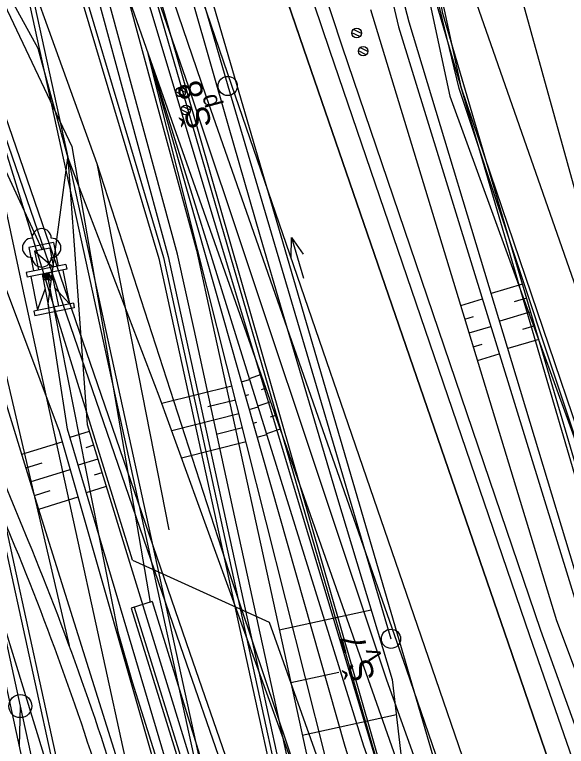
# Model space of a CAD drawing. Extents: x -439827 to -439102, y -1131353 to -1129707.
# Drawn here: x -439580.11 to -439551.42, y -1129995.75 to -1129957.67 of the extents above; entities that cross this region are included whole.
import ezdxf

# ---------------------------------------------------------------- set-up
doc = ezdxf.new("R2010")
doc.units = 0
for name, color, linetype in [('Vrstva 1', 7, 'Continuous'), ('Vrstva 10', 7, 'Continuous'), ('Vrstva 11', 7, 'Continuous'), ('Vrstva 15', 7, 'Continuous'), ('Vrstva 18', 7, 'Continuous'), ('Vrstva 20', 7, 'Continuous'), ('Vrstva 24', 7, 'Continuous'), ('Vrstva 25', 7, 'Continuous'), ('Vrstva 36', 7, 'Continuous'), ('Vrstva 4', 7, 'Continuous'), ('Vrstva 42', 7, 'Continuous'), ('Vrstva 45', 7, 'Continuous'), ('Vrstva 47', 7, 'Continuous'), ('Vrstva 49', 7, 'Continuous'), ('Vrstva 5', 7, 'Continuous'), ('Vrstva 50', 7, 'Continuous'), ('Vrstva 52', 7, 'Continuous'), ('Vrstva 57', 7, 'Continuous'), ('Vrstva 59', 7, 'Continuous'), ('Vrstva 61', 7, 'Continuous'), ('Vrstva 62', 7, 'Continuous'), ('Vrstva 63', 7, 'Continuous'), ('Vrstva 9', 7, 'Continuous')]:
    doc.layers.add(name, color=color, linetype=linetype)

# ---------------------------------------------------------------- blocks, each defined once
blk = doc.blocks.new('LAPAC_')
at = {"layer": 'Vrstva 1'}
for p, q in [((5, 10.49), (5, -10.5)), ((5, 10.49), (7.51, 10.49)), ((7.51, 10.49), (7.53, -10.5)), ((7.51, 8.5), (25.51, 8.49)), ((25.49, 8.48), (15.5, 2.5)), ((25.5, 10.47), (28, 10.48)), ((25.5, 10.47), (25.5, -10.5)), ((28, 10.48), (28.01, -10.48)), ((-7.5, 6.5), (4.99, 6.51)), ((-7.5, 6.5), (-7.49, -6.51)), ((-4.98, 4), (-5, -4)), ((-5, -4), (5, 4)), ((-4.98, 4), (5.01, 4)), ((7.51, 2.5), (25.5, 2.51)), ((7.51, 0), (28, 0)), ((7.51, -2.49), (25.5, -2.51)), ((25.51, -8.49), (15.52, -2.5)), ((-7.49, -6.51), (4.99, -6.51)), ((-5, -4), (4.99, -4)), ((5, -10.5), (7.53, -10.5)), ((7.51, -8.5), (25.51, -8.49)), ((25.5, -10.5), (28.01, -10.48))]:
    blk.add_line(p, q, dxfattribs=at)
for centre in [(8.3, 1.56), (8.3, 0.16), (8.67, -0.69), (9.89, 0.34), (10.54, 1.36), (8.76, -1.44), (9.88, -1.16)]:
    blk.add_circle(centre, 1, dxfattribs=at)

msp = doc.modelspace()

# ---------------------------------------------------------------- linework, layer by layer
at = {"layer": 'Vrstva 10'}
for p, q in [((-439553.692, -1129971.7), (-439555.32, -1129972.178)), ((-439556.908, -1129972.8), (-439555.784, -1129972.456)), ((-439553.482, -1129972.42), (-439554.13, -1129972.61)), ((-439556.69, -1129973.516), (-439556.24, -1129973.38)), ((-439553.27, -1129973.138), (-439554.884, -1129973.614)), ((-439556.472, -1129974.234), (-439555.342, -1129973.892)), ((-439553.06, -1129973.858), (-439553.704, -1129974.05)), ((-439556.254, -1129974.952), (-439555.802, -1129974.814)), ((-439552.848, -1129974.578), (-439554.452, -1129975.05)), ((-439556.034, -1129975.668), (-439554.902, -1129975.324)), ((-439567.29, -1129976.404), (-439567.902, -1129976.618)), ((-439568.312, -1129976.77), (-439567.89, -1129976.65)), ((-439568.806, -1129976.996), (-439572.45, -1129977.912)), ((-439567.04, -1129977.112), (-439567.294, -1129977.2)), ((-439568.106, -1129977.492), (-439567.93, -1129977.44)), ((-439568.622, -1129977.724), (-439570.052, -1129978.084)), ((-439566.79, -1129977.82), (-439567.456, -1129978.052)), ((-439567.902, -1129978.212), (-439567.446, -1129978.084)), ((-439568.44, -1129978.45), (-439571.938, -1129979.33)), ((-439566.542, -1129978.526), (-439566.818, -1129978.624)), ((-439567.698, -1129978.934), (-439567.508, -1129978.88)), ((-439576.226, -1129979.364), (-439577.232, -1129979.674)), ((-439568.258, -1129979.178), (-439569.626, -1129979.522)), ((-439567.494, -1129979.656), (-439567, -1129979.516)), ((-439566.294, -1129979.234), (-439567.01, -1129979.486)), ((-439579.738, -1129980.544), (-439577.63, -1129979.894)), ((-439576.006, -1129980.082), (-439576.41, -1129980.206)), ((-439568.074, -1129979.906), (-439571.424, -1129980.748)), ((-439579.516, -1129981.262), (-439578.678, -1129981.002)), ((-439575.784, -1129980.798), (-439576.806, -1129981.112)), ((-439579.294, -1129981.978), (-439577.218, -1129981.338)), ((-439575.564, -1129981.514), (-439575.974, -1129981.642)), ((-439579.074, -1129982.694), (-439578.25, -1129982.438)), ((-439575.342, -1129982.23), (-439576.378, -1129982.55)), ((-439578.852, -1129983.41), (-439576.81, -1129982.77))]:
    msp.add_line(p, q, dxfattribs=at)
msp.add_lwpolyline([(-439606.718, -1129878.884), (-439599.16, -1129893.286), (-439591.48, -1129910.122), (-439589.662, -1129921.096), (-439588.348, -1129928.69), (-439584.254, -1129940.826), (-439581.56, -1129949.574), (-439575.832, -1129965.416), (-439572.088, -1129984.488)], dxfattribs=at)
at = {"layer": 'Vrstva 11'}
for points in [[(-439631.45, -1129824.71), (-439623.296, -1129852.5), (-439607.812, -1129902.52), (-439594.486, -1129945.364), (-439588.77, -1129963.69), (-439582.318, -1129984.12), (-439576.384, -1130003.39), (-439571.028, -1130020.78), (-439569.524, -1130025.24)], [(-439572.89, -1130002.436), (-439578.954, -1129983.086), (-439585.23, -1129962.72)]]:
    msp.add_lwpolyline(points, dxfattribs=at)
at = {"layer": 'Vrstva 15'}
for p, q in [((-439562.072, -1129958.642), (-439562.488, -1129958.44)), ((-439562.158, -1129958.81), (-439562.568, -1129958.608)), ((-439561.82, -1129959.754), (-439562.232, -1129959.554)), ((-439561.736, -1129959.588), (-439562.152, -1129959.384)), ((-439571.222, -1129961.716), (-439571.638, -1129961.514)), ((-439571.308, -1129961.884), (-439571.718, -1129961.682)), ((-439571.044, -1129962.814), (-439571.456, -1129962.612)), ((-439570.96, -1129962.646), (-439571.376, -1129962.444)), ((-439566.346, -1129989.687), (-439561.562, -1129988.644)), ((-439565.749, -1129992.426), (-439563.249, -1129991.881)), ((-439565.152, -1129995.165), (-439560.254, -1129994.097))]:
    msp.add_line(p, q, dxfattribs=at)
for centre in [(-439562.319, -1129958.622), (-439561.982, -1129959.566), (-439571.47, -1129961.695), (-439571.207, -1129962.626)]:
    msp.add_circle(centre, 0.25, dxfattribs=at)
at = {"layer": 'Vrstva 18'}
msp.add_line((-439579.81, -1129993.657), (-439579.872, -1129995.717), dxfattribs=at)
msp.add_lwpolyline([(-439631.86, -1129744.036), (-439633.367, -1129748.063), (-439622.927, -1129795.938), (-439612.487, -1129843.813), (-439602.046, -1129891.688), (-439593.233, -1129932.103), (-439588.758, -1129952.621), (-439584.284, -1129973.139), (-439579.81, -1129993.657), (-439575.335, -1130014.174), (-439566.386, -1130055.21)], dxfattribs=at)
msp.add_circle((-439579.81, -1129993.657), 0.6, dxfattribs=at)
at = {"layer": 'Vrstva 20'}
for points in [[(-439511.068, -1130116.958), (-439519.726, -1130091.71), (-439522.682, -1130083.14), (-439529.956, -1130061.912), (-439534.024, -1130050.036), (-439543.72, -1130021.718), (-439554.45, -1129990.362), (-439564.874, -1129960.014), (-439575.322, -1129929.52)], [(-439514.996, -1130118.198), (-439526.684, -1130084.16), (-439534.114, -1130062.498), (-439537.924, -1130051.384), (-439547.688, -1130022.904), (-439558.398, -1129991.686), (-439568.82, -1129961.348), (-439579.29, -1129930.716)]]:
    msp.add_lwpolyline(points, dxfattribs=at)
at = {"layer": 'Vrstva 24'}
msp.add_line((-439580.77, -1129965.363), (-439578.671, -1129969.901), dxfattribs=at)
at = {"layer": 'Vrstva 36'}
for p, q in [((-439573.97, -1129986.06), (-439607.88, -1129876.57)), ((-439573.27, -1129886.24), (-439556.9, -1129961.42)), ((-439556.9, -1129961.42), (-439495.89, -1130141.59)), ((-439573.97, -1129986.06), (-439572.59, -1129986.69)), ((-439572.59, -1129986.69), (-439566.87, -1129989.29)), ((-439566.87, -1129989.29), (-439527.69, -1130099.7))]:
    msp.add_line(p, q, dxfattribs=at)
at = {"layer": 'Vrstva 4'}
for points in [[(-439452.672, -1130307.618), (-439463.136, -1130278.208), (-439473.444, -1130247.422), (-439485.028, -1130212.568), (-439496.122, -1130179.246), (-439507.47, -1130146.338), (-439516.97, -1130118.814), (-439528.894, -1130083.662), (-439539.69, -1130052.08), (-439549.11, -1130024.836), (-439560.748, -1129992.304), (-439571.06, -1129961.386), (-439580.88, -1129933.18), (-439592.05, -1129899.854), (-439602.118, -1129867.674), (-439610.398, -1129839.158), (-439617.774, -1129811.206), (-439624.664, -1129780.682), (-439629.998, -1129755.268)], [(-439452.072, -1130307.172), (-439462.466, -1130278.094), (-439473.084, -1130245.544), (-439484.196, -1130212.422), (-439495.494, -1130179.146), (-439506.764, -1130146.202), (-439516.426, -1130118.702), (-439528.244, -1130083.58), (-439539.098, -1130051.84), (-439548.434, -1130024.652), (-439559.722, -1129991.734), (-439570.14, -1129961.918), (-439579.974, -1129933.094), (-439590.708, -1129900.372), (-439601.098, -1129867.326), (-439609.248, -1129839.62), (-439616.746, -1129811.082), (-439623.958, -1129780.222), (-439629.3, -1129755.206)], [(-439445.336, -1130302.16), (-439455.084, -1130275.71), (-439466.188, -1130243.062), (-439488.304, -1130177.006), (-439499.622, -1130143.812), (-439508.924, -1130116.27), (-439521.236, -1130080.8), (-439532.228, -1130049.328), (-439540.848, -1130022.744), (-439552.746, -1129989.722), (-439563.07, -1129959.314), (-439572.718, -1129930.014), (-439582.84, -1129899.55), (-439593.798, -1129865.15), (-439602.014, -1129836.3), (-439609.444, -1129808.656), (-439617.162, -1129776.376), (-439620.256, -1129761.088), (-439620.404, -1129760.148)], [(-439446.102, -1130302.732), (-439455.792, -1130275.852), (-439466.676, -1130243.236), (-439477.16, -1130212.046), (-439488.92, -1130177.274), (-439500.288, -1130144.12), (-439509.364, -1130116.456), (-439521.914, -1130080.954), (-439532.724, -1130049.53), (-439541.918, -1130022.91), (-439553.308, -1129989.992), (-439563.72, -1129959.534), (-439573.732, -1129929.866), (-439583.77, -1129899.796), (-439594.604, -1129865.112), (-439602.866, -1129836.696), (-439610.248, -1129808.686), (-439617.812, -1129776.402), (-439620.902, -1129760.638), (-439620.878, -1129760.216)]]:
    msp.add_lwpolyline(points, dxfattribs=at)
at = {"layer": 'Vrstva 42'}
for points in [[(-439571.26, -1129941.374), (-439564.874, -1129960.014), (-439554.45, -1129990.362), (-439543.72, -1130021.718), (-439534.024, -1130050.036), (-439529.956, -1130061.912), (-439522.682, -1130083.14), (-439519.726, -1130091.71), (-439511.068, -1130116.958), (-439501.606, -1130144.528), (-439490.24, -1130177.636), (-439478.968, -1130210.544), (-439457.16, -1130275.562), (-439447.35, -1130302.89), (-439445.462, -1130308.388), (-439445.064, -1130309.558), (-439434.464, -1130340.548), (-439423.826, -1130371.538), (-439413.424, -1130401.962), (-439403.314, -1130431.488), (-439395.105, -1130455.427)], [(-439399.158, -1130456.267), (-439407.226, -1130432.678), (-439417.232, -1130403.478), (-439427.682, -1130373.028), (-439438.464, -1130341.588), (-439448.942, -1130311.012), (-439450.914, -1130305.246), (-439460.972, -1130277.082), (-439482.918, -1130211.888), (-439494.254, -1130178.768), (-439505.592, -1130145.672), (-439514.996, -1130118.198), (-439526.684, -1130084.16), (-439534.114, -1130062.498), (-439537.924, -1130051.384), (-439547.688, -1130022.904), (-439558.398, -1129991.686), (-439568.82, -1129961.348), (-439575.094, -1129942.992)]]:
    msp.add_lwpolyline(points, dxfattribs=at)
at = {"layer": 'Vrstva 45'}
msp.add_lwpolyline([(-439543.649, -1130001.679), (-439556.991, -1129961.508), (-439559.4, -1129951.517), (-439562.492, -1129936.521)], dxfattribs=at)
at = {"layer": 'Vrstva 47'}
for p, q in [((-439577.344, -1129932.554), (-439569.026, -1129961.378)), ((-439569.026, -1129961.378), (-439560.537, -1129990.152))]:
    msp.add_line(p, q, dxfattribs=at)
for centre in [(-439569.026, -1129961.378), (-439560.537, -1129990.152)]:
    msp.add_circle(centre, 0.5, dxfattribs=at)
at = {"layer": 'Vrstva 49'}
msp.add_line((-439565.704, -1129969.274), (-439565.081, -1129971.38), dxfattribs=at)
msp.add_lwpolyline([(-439565.732, -1129970.325), (-439565.704, -1129969.274), (-439565.109, -1129970.141)], dxfattribs=at)
at = {"layer": 'Vrstva 5'}
for points in [[(-439524.128, -1130104.684), (-439542.36, -1130053.899), (-439560.483, -1129998.857), (-439575.708, -1129945.714), (-439590.289, -1129890.237), (-439603.222, -1129834.191), (-439614.978, -1129781.165), (-439626.657, -1129727.981), (-439631.05, -1129707.012)], [(-439600.718, -1129837.291), (-439598.553, -1129847.054), (-439596.345, -1129856.808), (-439594.102, -1129866.554), (-439591.818, -1129876.291), (-439589.494, -1129886.019), (-439587.117, -1129895.735), (-439584.686, -1129905.44), (-439582.203, -1129915.134), (-439580.689, -1129920.945), (-439579.669, -1129924.816), (-439577.082, -1129934.487), (-439574.443, -1129944.147), (-439571.752, -1129953.795), (-439569.009, -1129963.432), (-439567.338, -1129969.208), (-439566.214, -1129973.057), (-439563.366, -1129982.671), (-439560.466, -1129992.274), (-439559.308, -1130002.256), (-439558.201, -1130012.25), (-439555.572, -1130021.911), (-439553.075, -1130031.602), (-439552.175, -1130035.027)], [(-439556.38, -1130040.02), (-439557.995, -1130032.675), (-439560.126, -1130022.905), (-439562.257, -1130013.134), (-439564.387, -1130003.364), (-439566.518, -1129993.593), (-439568.649, -1129983.823), (-439570.779, -1129974.053), (-439571.634, -1129970.132), (-439573.209, -1129964.322), (-439575.828, -1129954.658), (-439578.447, -1129944.994), (-439581.067, -1129935.33), (-439583.686, -1129925.667), (-439584.73, -1129921.813), (-439586.006, -1129915.963), (-439588.136, -1129906.193), (-439590.267, -1129896.422), (-439592.398, -1129886.652), (-439594.528, -1129876.882), (-439596.659, -1129867.111), (-439598.79, -1129857.341), (-439600.92, -1129847.57), (-439603.051, -1129837.8)], [(-439587.96, -1129916.389), (-439586.682, -1129922.251), (-439585.536, -1129926.096), (-439582.673, -1129935.706), (-439579.809, -1129945.317), (-439576.946, -1129954.927), (-439574.082, -1129964.538), (-439572.364, -1129970.304), (-439571.512, -1129974.212), (-439569.381, -1129983.983), (-439567.251, -1129993.753), (-439565.12, -1130003.524), (-439562.989, -1130013.294), (-439560.859, -1130023.064), (-439558.728, -1130032.835), (-439557.22, -1130039.748), (-439556.597, -1130042.605), (-439554.467, -1130052.375), (-439552.336, -1130062.146), (-439550.379, -1130071.121)], [(-439586.934, -1129922.311), (-439586.926, -1129922.305), (-439585.78, -1129926.149), (-439582.917, -1129935.76), (-439580.053, -1129945.37), (-439577.19, -1129954.981), (-439574.327, -1129964.591), (-439572.609, -1129970.358), (-439571.756, -1129974.266), (-439569.626, -1129984.036), (-439567.495, -1129993.806), (-439565.364, -1130003.577), (-439563.234, -1130013.347), (-439561.103, -1130023.118), (-439558.972, -1130032.888), (-439557.465, -1130039.801), (-439556.842, -1130042.658), (-439554.711, -1130052.429), (-439552.58, -1130062.199), (-439551.985, -1130064.928)], [(-439584.168, -1129925.797), (-439581.549, -1129935.461), (-439578.93, -1129945.125), (-439576.311, -1129954.789), (-439573.692, -1129964.453), (-439572.12, -1129970.251), (-439571.268, -1129974.159), (-439569.137, -1129983.93), (-439567.006, -1129993.7), (-439564.876, -1130003.47), (-439562.745, -1130013.241), (-439560.614, -1130023.011), (-439558.484, -1130032.781), (-439556.976, -1130039.694), (-439556.353, -1130042.552), (-439554.222, -1130052.322), (-439552.092, -1130062.093), (-439551.741, -1130063.699)], [(-439582.703, -1129925.478), (-439580.084, -1129935.142), (-439577.464, -1129944.805), (-439574.845, -1129954.469), (-439572.226, -1129964.133), (-439570.654, -1129969.931), (-439569.802, -1129973.84), (-439567.672, -1129983.61), (-439565.541, -1129993.38), (-439563.41, -1130003.151), (-439561.28, -1130012.921), (-439559.149, -1130022.691), (-439557.018, -1130032.462), (-439555.511, -1130039.375), (-439554.888, -1130042.232), (-439552.757, -1130052.003), (-439550.626, -1130061.773), (-439548.496, -1130071.543), (-439547.692, -1130075.226)], [(-439585.829, -1129926.16), (-439583.699, -1129935.93), (-439581.568, -1129945.7), (-439579.437, -1129955.471), (-439577.307, -1129965.241), (-439576.028, -1129971.103), (-439575.176, -1129975.011), (-439573.045, -1129984.782), (-439570.915, -1129994.552), (-439568.784, -1130004.323), (-439566.653, -1130014.093), (-439564.523, -1130023.863), (-439562.392, -1130033.634), (-439560.884, -1130040.547), (-439560.261, -1130043.404), (-439558.131, -1130053.174), (-439556, -1130062.945), (-439553.869, -1130072.715), (-439551.739, -1130082.486), (-439549.608, -1130092.256), (-439547.477, -1130102.026), (-439545.347, -1130111.797)], [(-439586.073, -1129926.213), (-439583.943, -1129935.983), (-439581.812, -1129945.754), (-439579.682, -1129955.524), (-439577.551, -1129965.294), (-439576.272, -1129971.157), (-439575.42, -1129975.065), (-439573.29, -1129984.835), (-439571.159, -1129994.605), (-439569.028, -1130004.376), (-439566.898, -1130014.146), (-439564.767, -1130023.917), (-439562.636, -1130033.687), (-439561.129, -1130040.6), (-439560.506, -1130043.457), (-439558.375, -1130053.228), (-439556.244, -1130062.998), (-439554.114, -1130072.769), (-439551.983, -1130082.539), (-439549.852, -1130092.309), (-439547.722, -1130102.08), (-439545.591, -1130111.85)], [(-439589.493, -1129926.959), (-439587.362, -1129936.729), (-439585.232, -1129946.499), (-439583.101, -1129956.27), (-439580.97, -1129966.04), (-439579.692, -1129971.902), (-439578.84, -1129975.81), (-439576.709, -1129985.581), (-439574.578, -1129995.351), (-439572.448, -1130005.122), (-439570.317, -1130014.892), (-439568.186, -1130024.662), (-439566.056, -1130034.433), (-439564.548, -1130041.346), (-439563.925, -1130044.203), (-439561.794, -1130053.973), (-439559.664, -1130063.744), (-439557.533, -1130073.514), (-439555.402, -1130083.285), (-439553.272, -1130093.055), (-439551.141, -1130102.825), (-439549.01, -1130112.596)], [(-439592.913, -1129927.704), (-439590.782, -1129937.475), (-439588.651, -1129947.245), (-439586.521, -1129957.015), (-439584.39, -1129966.786), (-439583.112, -1129972.648), (-439582.259, -1129976.556), (-439580.129, -1129986.327), (-439577.998, -1129996.097), (-439575.867, -1130005.867), (-439573.737, -1130015.638), (-439571.606, -1130025.408), (-439569.475, -1130035.178), (-439567.968, -1130042.091), (-439567.345, -1130044.949), (-439565.214, -1130054.719), (-439563.083, -1130064.49), (-439560.953, -1130074.26), (-439558.822, -1130084.03), (-439556.691, -1130093.801), (-439554.561, -1130103.571), (-439552.43, -1130113.341)], [(-439594.623, -1129928.077), (-439592.492, -1129937.848), (-439590.361, -1129947.618), (-439588.231, -1129957.388), (-439586.1, -1129967.159), (-439584.822, -1129973.021), (-439583.969, -1129976.929), (-439581.839, -1129986.699), (-439579.708, -1129996.47), (-439577.577, -1130006.24), (-439575.447, -1130016.011), (-439573.316, -1130025.781), (-439571.185, -1130035.551), (-439569.678, -1130042.464), (-439569.055, -1130045.322), (-439566.924, -1130055.092), (-439564.793, -1130064.862), (-439562.663, -1130074.633), (-439560.532, -1130084.403), (-439558.401, -1130094.174), (-439556.271, -1130103.944), (-439554.14, -1130113.714)], [(-439593.157, -1129927.758), (-439591.026, -1129937.528), (-439588.896, -1129947.298), (-439586.765, -1129957.069), (-439584.634, -1129966.839), (-439583.356, -1129972.701), (-439582.504, -1129976.609), (-439580.373, -1129986.38), (-439578.242, -1129996.15), (-439576.112, -1130005.921), (-439573.981, -1130015.691), (-439571.85, -1130025.461), (-439569.72, -1130035.232), (-439568.212, -1130042.145), (-439567.589, -1130045.002), (-439565.458, -1130054.772), (-439563.328, -1130064.543), (-439561.197, -1130074.313), (-439559.066, -1130084.084), (-439556.936, -1130093.854), (-439554.805, -1130103.624), (-439552.674, -1130113.395)]]:
    msp.add_lwpolyline(points, dxfattribs=at)
at = {"layer": 'Vrstva 50'}
msp.add_line((-439578.732, -1129969.804), (-439578.66, -1129969.804), dxfattribs=at)
for centre, start, end in [((-439578.701, -1129969.303), 0, 180), ((-439579.201, -1129969.803), 90, 270), ((-439578.201, -1129969.803), 270, 90), ((-439578.701, -1129970.303), 180, 0)]:
    msp.add_arc(centre, 0.5, start, end, dxfattribs=at)
at = {"layer": 'Vrstva 52'}
for p, q in [((-439583.644, -1129950.788), (-439577.136, -1129964.538)), ((-439577.136, -1129964.538), (-439573.056, -1129988.268)), ((-439582.952, -1129966.168), (-439577.266, -1129990.506)), ((-439579.398, -1129985.038), (-439584.406, -1129972.9)), ((-439580.09, -1129985.324), (-439585.118, -1129973.142)), ((-439578.032, -1129973.138), (-439574.742, -1129989.788)), ((-439572.956, -1129988.212), (-439574.054, -1129988.552))]:
    msp.add_line(p, q, dxfattribs=at)
for points in [[(-439572.956, -1129988.212), (-439566.758, -1130008.234)], [(-439574.054, -1129988.552), (-439567.864, -1130008.55)], [(-439573.89, -1129988.502), (-439570.934, -1129998.056)], [(-439574.742, -1129989.788), (-439574, -1129992.396), (-439568.824, -1130008.828)]]:
    msp.add_lwpolyline(points, dxfattribs=at)
for radius in [151.25, 150.5]:
    msp.add_arc((-439719.223, -1130042.705), radius, 16.09885, 22.41188, dxfattribs=at)
at = {"layer": 'Vrstva 57'}
for p, q in [((-439615.997, -1129861.04), (-439571.326, -1129991.012)), ((-439571.326, -1129991.012), (-439532.649, -1130102.737))]:
    msp.add_line(p, q, dxfattribs=at)
at = {"layer": 'Vrstva 59'}
for p, q in [((-439615.666, -1129860.926), (-439570.995, -1129990.899)), ((-439570.995, -1129990.898), (-439532.318, -1130102.623))]:
    msp.add_line(p, q, dxfattribs=at)
msp.add_lwpolyline([(-439565.323, -1129925.255), (-439558.917, -1129955.176), (-439557.476, -1129961.905), (-439549.066, -1129985.001)], dxfattribs=at)
at = {"layer": 'Vrstva 61'}
for p, q in [((-439547.146, -1129994.737), (-439562.474, -1129942.35)), ((-439573.227, -1129945.323), (-439557.81, -1129998.142))]:
    msp.add_line(p, q, dxfattribs=at)
at = {"layer": 'Vrstva 62'}
msp.add_line((-439560.603, -1129998.786), (-439575.875, -1129946.07), dxfattribs=at)
at = {"layer": 'Vrstva 63'}
msp.add_lwpolyline([(-439559.899, -1130001.173), (-439569.713, -1129968.453), (-439577.958, -1129940.931), (-439581.389, -1129927.721), (-439587.866, -1129899.446), (-439590.167, -1129890.323), (-439596.266, -1129862.915), (-439602.978, -1129834.556), (-439615.089, -1129778.896), (-439619.056, -1129758.708), (-439624.106, -1129738.276), (-439628.163, -1129719.403), (-439630.545, -1129707.012)], dxfattribs=at)
at = {"layer": 'Vrstva 9'}
for p, q in [((-439573.156, -1129959.7), (-439550.138, -1130025.226)), ((-439578.362, -1129972.718), (-439577.34, -1129965.12))]:
    msp.add_line(p, q, dxfattribs=at)
for points in [[(-439615.016, -1129861.902), (-439609.016, -1129872.388), (-439598.672, -1129902.048), (-439593.08, -1129922.412), (-439591.246, -1129928.438), (-439589.858, -1129932.272), (-439590.514, -1129935.246), (-439587.63, -1129940.776), (-439586.318, -1129945.922), (-439578.898, -1129959.416), (-439577.34, -1129965.12), (-439572.6, -1129977.504), (-439565.568, -1129996.93)], [(-439539.1, -1130013.316), (-439547.926, -1129991.32), (-439557.834, -1129957.61), (-439562.26, -1129933.836), (-439563.77, -1129920.72)], [(-439563.77, -1129920.72), (-439558.54, -1129929.636), (-439556.21, -1129956.716), (-439544.386, -1129990.572), (-439539.1, -1130013.316)], [(-439583.996, -1129927.66), (-439580.782, -1129937.88), (-439573.156, -1129959.7)], [(-439558.54, -1129929.636), (-439553.914, -1129956.15), (-439544.386, -1129990.572)], [(-439565.696, -1129934.664), (-439560.14, -1129958.304), (-439549.714, -1129992.178), (-439541.66, -1130014.164), (-439534.13, -1130036.788), (-439529.434, -1130049.122)], [(-439529.434, -1130049.122), (-439533.642, -1130036.612), (-439541.214, -1130013.966), (-439549.356, -1129991.93), (-439559.582, -1129958.054), (-439565.696, -1129934.664)], [(-439588.27, -1129946.636), (-439583.488, -1129962.072), (-439583.98, -1129962.938), (-439582.788, -1129966.044), (-439577.788, -1129979.34), (-439572.16, -1129999.082), (-439566.194, -1130018.824), (-439554.92, -1130053.378)], [(-439539.78, -1130021.546), (-439551.914, -1129989.212), (-439561.59, -1129957.412)], [(-439539.976, -1130066.112), (-439543.636, -1130055.94), (-439548.718, -1130040.922), (-439555.81, -1130018.284), (-439563.966, -1129996.25), (-439573.156, -1129959.7)], [(-439573.156, -1129959.7), (-439562.928, -1129995.746), (-439555.81, -1130018.284)], [(-439573.156, -1129959.7), (-439561.968, -1129995.718), (-439554.008, -1130017.84), (-439547.068, -1130040.406), (-439541.34, -1130055.714), (-439538.356, -1130063.796)], [(-439577.34, -1129965.12), (-439576.34, -1129978.998), (-439570.26, -1129998.734), (-439564.65, -1130018.494)], [(-439575.832, -1129965.416), (-439568.974, -1129986.65), (-439562.208, -1130006.75), (-439555.4, -1130027.656), (-439549.7, -1130045.104), (-439543.224, -1130064.878), (-439534.136, -1130092.886), (-439531.324, -1130101.162), (-439529.482, -1130100.572)], [(-439554.92, -1130053.378), (-439565.49, -1130018.736), (-439571.516, -1129998.944), (-439577.362, -1129979.234), (-439578.362, -1129972.718)]]:
    msp.add_lwpolyline(points, dxfattribs=at)

# ---------------------------------------------------------------- block references
at = {"layer": 'Vrstva 25', "xscale": 0.1, "yscale": 0.10000000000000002, "rotation": -78.79788058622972}
msp.add_blockref('LAPAC_', (-439578.575, -1129970.389), dxfattribs=at)

# ---------------------------------------------------------------- texts
at = {"layer": 'Vrstva 49'}
for s, height, p in [('Š 8', 1.25, (-439569.832, -1129963.418)), ('p', 0.938, (-439569.48, -1129962.398)), ('Š 7', 1.25, (-439561.343, -1129992.191)), ('v', 0.937, (-439560.991, -1129991.172))]:
    msp.add_text(s, height=height, rotation=104.8992, dxfattribs=at).set_placement(p)

doc.saveas('drawing.dxf')
